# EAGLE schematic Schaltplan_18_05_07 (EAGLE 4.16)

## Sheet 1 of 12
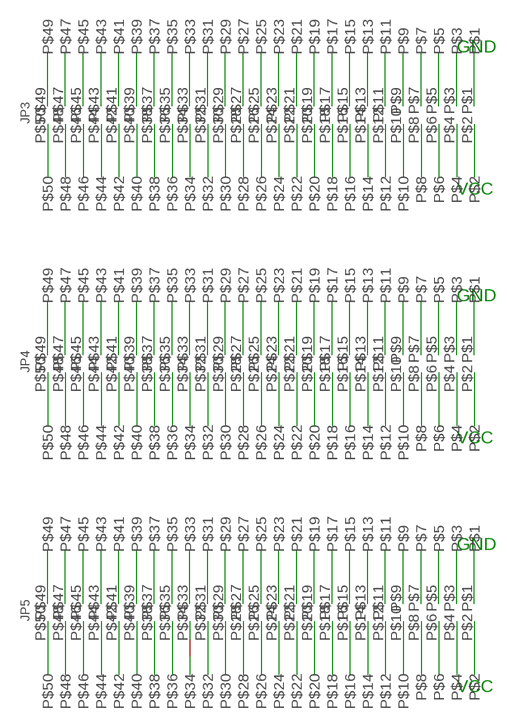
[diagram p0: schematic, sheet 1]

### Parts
JP3  CONN_50POL  [CONN_50POL]
JP4  CONN_50POL  [CONN_50POL]
JP5  CONN_50POL  [CONN_50POL]

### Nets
/NMI: JP3.P$45 ; also sheet 2
/RD: JP3.P$37 ; also sheet 2
/RDY: JP5.P$14 ; also sheet 2
/RESI: JP3.P$41 ; also sheet 2
/RESO: JP3.P$43 ; also sheet 2
/WR: JP3.P$42 ; also sheet 2
A0: JP3.P$6 ; also sheet 2
A1: JP3.P$8 ; also sheet 2
A2: JP3.P$10 ; also sheet 2
A3: JP3.P$12 ; also sheet 2
A4: JP3.P$14 ; also sheet 2
A5: JP3.P$16 ; also sheet 2
A6: JP3.P$18 ; also sheet 2
A7: JP3.P$20 ; also sheet 2
A8: JP3.P$22 ; also sheet 2
A9: JP3.P$24 ; also sheet 2
A10: JP3.P$26 ; also sheet 2
A11: JP3.P$28 ; also sheet 2
A12: JP3.P$30 ; also sheet 2
A13: JP3.P$32 ; also sheet 2
A14: JP3.P$34 ; also sheet 2
A15: JP3.P$36 ; also sheet 2
A16: JP3.P$38 ; also sheet 2
A17: JP3.P$40 ; also sheet 2
A18: JP3.P$46 ; also sheet 2
A19: JP3.P$48 ; also sheet 2
A20: JP3.P$50 ; also sheet 2
A21: JP3.P$49 ; also sheet 2,10
A22: JP3.P$47 ; also sheet 2,10
A23: JP5.P$13 ; also sheet 2
ALE: JP3.P$39 ; also sheet 2
D0: JP3.P$5 ; also sheet 2
D1: JP3.P$7 ; also sheet 2
D2: JP3.P$9 ; also sheet 2
D3: JP3.P$11 ; also sheet 2
D4: JP3.P$13 ; also sheet 2,7
D5: JP3.P$15 ; also sheet 2
D6: JP3.P$17 ; also sheet 2
D7: JP3.P$19 ; also sheet 2
D8: JP3.P$21 ; also sheet 2
D9: JP3.P$23 ; also sheet 2
D10: JP3.P$25 ; also sheet 2
D11: JP3.P$27 ; also sheet 2
D12: JP3.P$29 ; also sheet 2
D13: JP3.P$31 ; also sheet 2
D14: JP3.P$33 ; also sheet 2
D15: JP3.P$35 ; also sheet 2
GND: JP3.P$1 JP3.P$3 JP4.P$1 JP4.P$3 JP5.P$1 JP5.P$3 ; also sheet 2,3,5,6,7,8,9,10,11,12
N$92: JP4.P$18
N$93: JP4.P$16
N$142: JP5.P$18
N$143: JP5.P$16
P2.0: JP4.P$19 ; also sheet 2,8
P2.1: JP4.P$21 ; also sheet 2,8
P2.2: JP4.P$23 ; also sheet 2,8
P2.3: JP4.P$25 ; also sheet 2,8
P2.4: JP4.P$27 ; also sheet 2,8
P2.5: JP4.P$29 ; also sheet 2,8
P2.6: JP4.P$31 ; also sheet 2,8
P2.7: JP4.P$33 ; also sheet 2,8
P2.8: JP4.P$35 ; also sheet 2,9
P2.9: JP4.P$37 ; also sheet 2
P2.10: JP4.P$39 ; also sheet 2
P2.11: JP4.P$41 ; also sheet 2
P2.12: JP4.P$43 ; also sheet 2
P2.13: JP4.P$45 ; also sheet 2
P2.14: JP4.P$47 ; also sheet 2
P2.15: JP4.P$49 ; also sheet 2
P3.0: JP4.P$20 ; also sheet 2
P3.1: JP4.P$22 ; also sheet 2
P3.2: JP4.P$24 ; also sheet 2
P3.3: JP4.P$26 ; also sheet 2,9
P3.4: JP4.P$28 ; also sheet 2,11
P3.5: JP4.P$30 ; also sheet 2,11
P3.6: JP4.P$32 ; also sheet 2,11
P3.7: JP4.P$34 ; also sheet 2,11
P3.8: JP4.P$36 ; also sheet 2,11
P3.9: JP4.P$38 ; also sheet 2,11
P3.10: JP4.P$40 ; also sheet 2,11
P3.11: JP4.P$42 ; also sheet 2,11
P3.12: JP3.P$44 JP4.P$44 ; also sheet 2
P3.13: JP4.P$46 ; also sheet 2
P3.14: JP4.P$48
P3.15: JP4.P$50 ; also sheet 2
P5.0: JP4.P$5 JP5.P$19 ; also sheet 2,6
P5.1: JP4.P$6 JP5.P$21 ; also sheet 2,6
P5.2: JP4.P$7 JP5.P$23 ; also sheet 2,6
P5.3: JP4.P$8 JP5.P$25 ; also sheet 2,6
P5.4: JP4.P$9 JP5.P$27 ; also sheet 2,6
P5.5: JP4.P$10 JP5.P$29 ; also sheet 2,6
P5.6: JP4.P$11 JP5.P$31 ; also sheet 2,6
P5.7: JP4.P$12 JP5.P$33 ; also sheet 2,6
P5.8: JP4.P$13 JP5.P$35 ; also sheet 2,9
P5.9: JP4.P$14 JP5.P$37 ; also sheet 2,9
P5.10: JP5.P$39 ; also sheet 2,4
P5.11: JP5.P$41 ; also sheet 2
P5.12: JP5.P$43 ; also sheet 2,4
P5.13: JP5.P$45 ; also sheet 2
P5.14: JP5.P$47 ; also sheet 2
P5.15: JP5.P$49 ; also sheet 2
P6.0: JP5.P$5 ; also sheet 2
P6.1: JP5.P$6 ; also sheet 2
P6.2: JP5.P$7 ; also sheet 2
P6.3: JP5.P$8 ; also sheet 2
P6.4: JP5.P$9 ; also sheet 2
P6.5: JP5.P$10 ; also sheet 2
P6.6: JP5.P$11 ; also sheet 2
P6.7: JP5.P$12 ; also sheet 2
P7.0: JP5.P$20 ; also sheet 2
P7.1: JP5.P$22 ; also sheet 2
P7.2: JP5.P$24 ; also sheet 2
P7.3: JP5.P$26 ; also sheet 2
P7.4: JP5.P$28 ; also sheet 2,9
P7.5: JP5.P$30 ; also sheet 2,9
P7.6: JP5.P$32 ; also sheet 2,9
P7.7: JP5.P$34 ; also sheet 2,9
P8.0: JP5.P$36 ; also sheet 2
P8.1: JP5.P$38 ; also sheet 2
P8.2: JP5.P$40 ; also sheet 2
P8.3: JP5.P$42 ; also sheet 2
P8.4: JP5.P$44 ; also sheet 2
P8.5: JP5.P$46 ; also sheet 2
P8.6: JP5.P$48 ; also sheet 2
P8.7: JP5.P$50 ; also sheet 2
VAGND: JP4.P$15 JP5.P$15 ; also sheet 2,3,4
VAREF: JP4.P$17 JP5.P$17 ; also sheet 2,3
VCC2: JP3.P$2 JP3.P$4 JP4.P$2 JP4.P$4 JP5.P$2 JP5.P$4 ; also sheet 3,4,6,8,9,10,11

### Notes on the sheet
- GND
- VCC
- GND
- VCC
- GND
- VCC

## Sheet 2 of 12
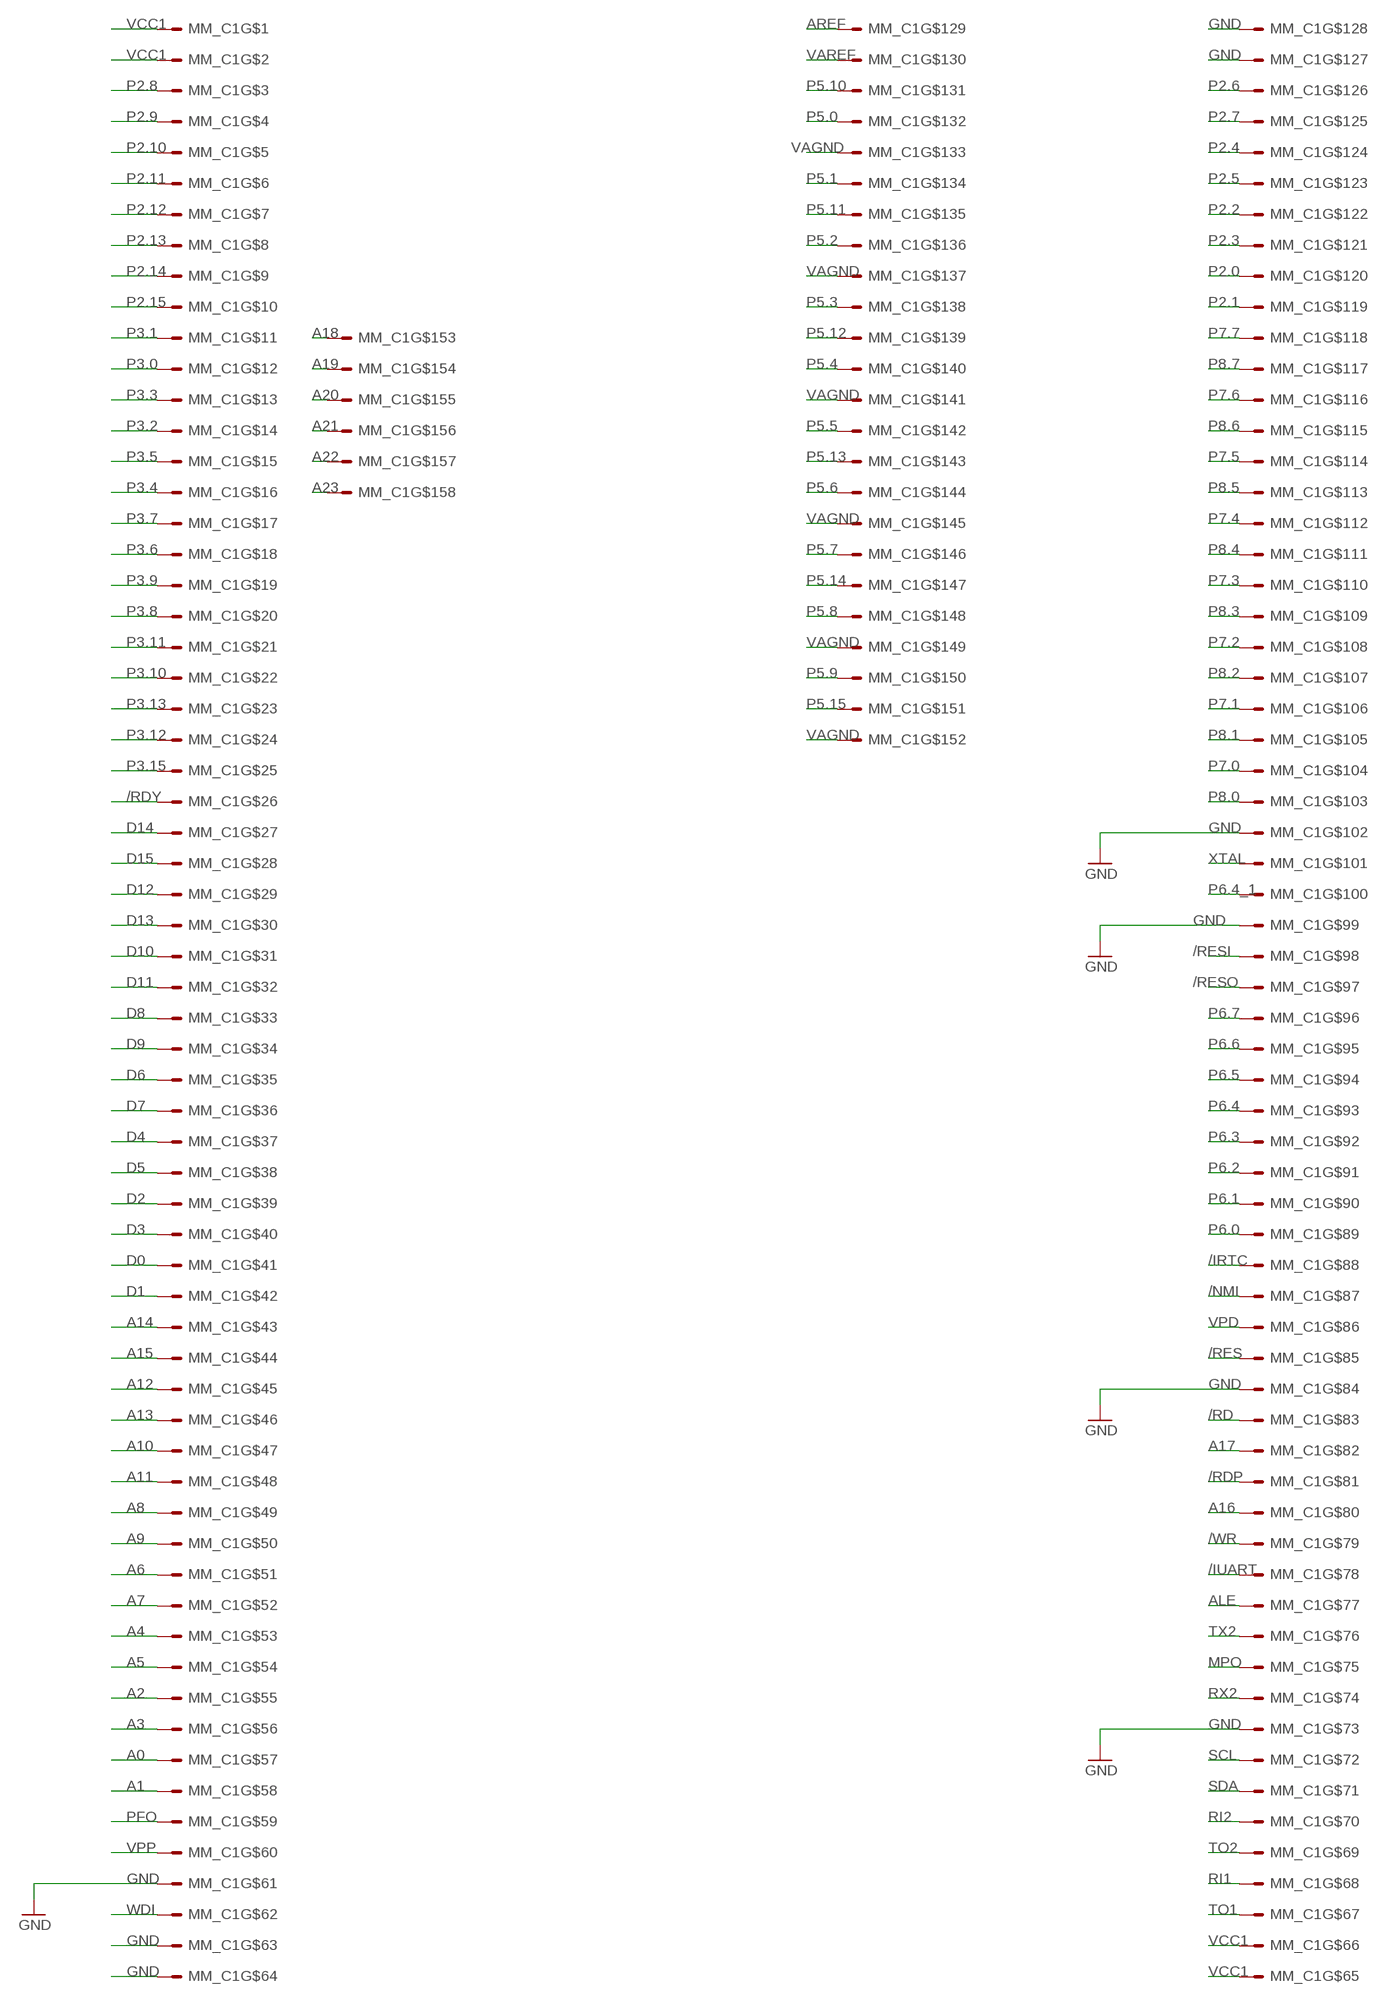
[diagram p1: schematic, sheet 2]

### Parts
MM_C1  MM_C167  [MM_GES]

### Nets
/IRTC: MM_C1.88 ; also sheet 12
/IUART: MM_C1.78
/NMI: MM_C1.87 ; also sheet 1
/RD: MM_C1.83 ; also sheet 1
/RDP: MM_C1.81
/RDY: MM_C1.26 ; also sheet 1
/RES: MM_C1.85 ; also sheet 7
/RESI: MM_C1.98 ; also sheet 1
/RESO: MM_C1.97 ; also sheet 1
/WR: MM_C1.79 ; also sheet 1
A0: MM_C1.57 ; also sheet 1
A1: MM_C1.58 ; also sheet 1
A2: MM_C1.55 ; also sheet 1
A3: MM_C1.56 ; also sheet 1
A4: MM_C1.53 ; also sheet 1
A5: MM_C1.54 ; also sheet 1
A6: MM_C1.51 ; also sheet 1
A7: MM_C1.52 ; also sheet 1
A8: MM_C1.49 ; also sheet 1
A9: MM_C1.50 ; also sheet 1
A10: MM_C1.47 ; also sheet 1
A11: MM_C1.48 ; also sheet 1
A12: MM_C1.45 ; also sheet 1
A13: MM_C1.46 ; also sheet 1
A14: MM_C1.43 ; also sheet 1
A15: MM_C1.44 ; also sheet 1
A16: MM_C1.80 ; also sheet 1
A17: MM_C1.82 ; also sheet 1
A18: MM_C1.153 ; also sheet 1
A19: MM_C1.154 ; also sheet 1
A20: MM_C1.155 ; also sheet 1
A21: MM_C1.156 ; also sheet 1,10
A22: MM_C1.157 ; also sheet 1,10
A23: MM_C1.158 ; also sheet 1
ALE: MM_C1.77 ; also sheet 1
AREF: MM_C1.129
D0: MM_C1.41 ; also sheet 1
D1: MM_C1.42 ; also sheet 1
D2: MM_C1.39 ; also sheet 1
D3: MM_C1.40 ; also sheet 1
D4: MM_C1.37 ; also sheet 1,7
D5: MM_C1.38 ; also sheet 1
D6: MM_C1.35 ; also sheet 1
D7: MM_C1.36 ; also sheet 1
D8: MM_C1.33 ; also sheet 1
D9: MM_C1.34 ; also sheet 1
D10: MM_C1.31 ; also sheet 1
D11: MM_C1.32 ; also sheet 1
D12: MM_C1.29 ; also sheet 1
D13: MM_C1.30 ; also sheet 1
D14: MM_C1.27 ; also sheet 1
D15: MM_C1.28 ; also sheet 1
GND: MM_C1.61 MM_C1.63 MM_C1.64 MM_C1.73 MM_C1.84 MM_C1.99 MM_C1.102 MM_C1.127 MM_C1.128 ; also sheet 1,3,5,6,7,8,9,10,11,12
MPO: MM_C1.75
P2.0: MM_C1.120 ; also sheet 1,8
P2.1: MM_C1.119 ; also sheet 1,8
P2.2: MM_C1.122 ; also sheet 1,8
P2.3: MM_C1.121 ; also sheet 1,8
P2.4: MM_C1.124 ; also sheet 1,8
P2.5: MM_C1.123 ; also sheet 1,8
P2.6: MM_C1.126 ; also sheet 1,8
P2.7: MM_C1.125 ; also sheet 1,8
P2.8: MM_C1.3 ; also sheet 1,9
P2.9: MM_C1.4 ; also sheet 1
P2.10: MM_C1.5 ; also sheet 1
P2.11: MM_C1.6 ; also sheet 1
P2.12: MM_C1.7 ; also sheet 1
P2.13: MM_C1.8 ; also sheet 1
P2.14: MM_C1.9 ; also sheet 1
P2.15: MM_C1.10 ; also sheet 1
P3.0: MM_C1.12 ; also sheet 1
P3.1: MM_C1.11 ; also sheet 1
P3.2: MM_C1.14 ; also sheet 1
P3.3: MM_C1.13 ; also sheet 1,9
P3.4: MM_C1.16 ; also sheet 1,11
P3.5: MM_C1.15 ; also sheet 1,11
P3.6: MM_C1.18 ; also sheet 1,11
P3.7: MM_C1.17 ; also sheet 1,11
P3.8: MM_C1.20 ; also sheet 1,11
P3.9: MM_C1.19 ; also sheet 1,11
P3.10: MM_C1.22 ; also sheet 1,11
P3.11: MM_C1.21 ; also sheet 1,11
P3.12: MM_C1.24 ; also sheet 1
P3.13: MM_C1.23 ; also sheet 1
P3.15: MM_C1.25 ; also sheet 1
P5.0: MM_C1.132 ; also sheet 1,6
P5.1: MM_C1.134 ; also sheet 1,6
P5.2: MM_C1.136 ; also sheet 1,6
P5.3: MM_C1.138 ; also sheet 1,6
P5.4: MM_C1.140 ; also sheet 1,6
P5.5: MM_C1.142 ; also sheet 1,6
P5.6: MM_C1.144 ; also sheet 1,6
P5.7: MM_C1.146 ; also sheet 1,6
P5.8: MM_C1.148 ; also sheet 1,9
P5.9: MM_C1.150 ; also sheet 1,9
P5.10: MM_C1.131 ; also sheet 1,4
P5.11: MM_C1.135 ; also sheet 1
P5.12: MM_C1.139 ; also sheet 1,4
P5.13: MM_C1.143 ; also sheet 1
P5.14: MM_C1.147 ; also sheet 1
P5.15: MM_C1.151 ; also sheet 1
P6.0: MM_C1.89 ; also sheet 1
P6.1: MM_C1.90 ; also sheet 1
P6.2: MM_C1.91 ; also sheet 1
P6.3: MM_C1.92 ; also sheet 1
P6.4: MM_C1.93 ; also sheet 1
P6.4_1: MM_C1.100
P6.5: MM_C1.94 ; also sheet 1
P6.6: MM_C1.95 ; also sheet 1
P6.7: MM_C1.96 ; also sheet 1
P7.0: MM_C1.104 ; also sheet 1
P7.1: MM_C1.106 ; also sheet 1
P7.2: MM_C1.108 ; also sheet 1
P7.3: MM_C1.110 ; also sheet 1
P7.4: MM_C1.112 ; also sheet 1,9
P7.5: MM_C1.114 ; also sheet 1,9
P7.6: MM_C1.116 ; also sheet 1,9
P7.7: MM_C1.118 ; also sheet 1,9
P8.0: MM_C1.103 ; also sheet 1
P8.1: MM_C1.105 ; also sheet 1
P8.2: MM_C1.107 ; also sheet 1
P8.3: MM_C1.109 ; also sheet 1
P8.4: MM_C1.111 ; also sheet 1
P8.5: MM_C1.113 ; also sheet 1
P8.6: MM_C1.115 ; also sheet 1
P8.7: MM_C1.117 ; also sheet 1
PFO: MM_C1.59
RI1: MM_C1.68 ; also sheet 5
RI2: MM_C1.70 ; also sheet 5
RX2: MM_C1.74
SCL: MM_C1.72 ; also sheet 12
SDA: MM_C1.71 ; also sheet 12
TO1: MM_C1.67 ; also sheet 5
TO2: MM_C1.69 ; also sheet 5
TX2: MM_C1.76
VAGND: MM_C1.133 MM_C1.137 MM_C1.141 MM_C1.145 MM_C1.149 MM_C1.152 ; also sheet 1,3,4
VAREF: MM_C1.130 ; also sheet 1,3
VCC1: MM_C1.1 MM_C1.2 MM_C1.65 MM_C1.66 ; also sheet 3
VPD: MM_C1.86
VPP: MM_C1.60
WDI: MM_C1.62
XTAL: MM_C1.101

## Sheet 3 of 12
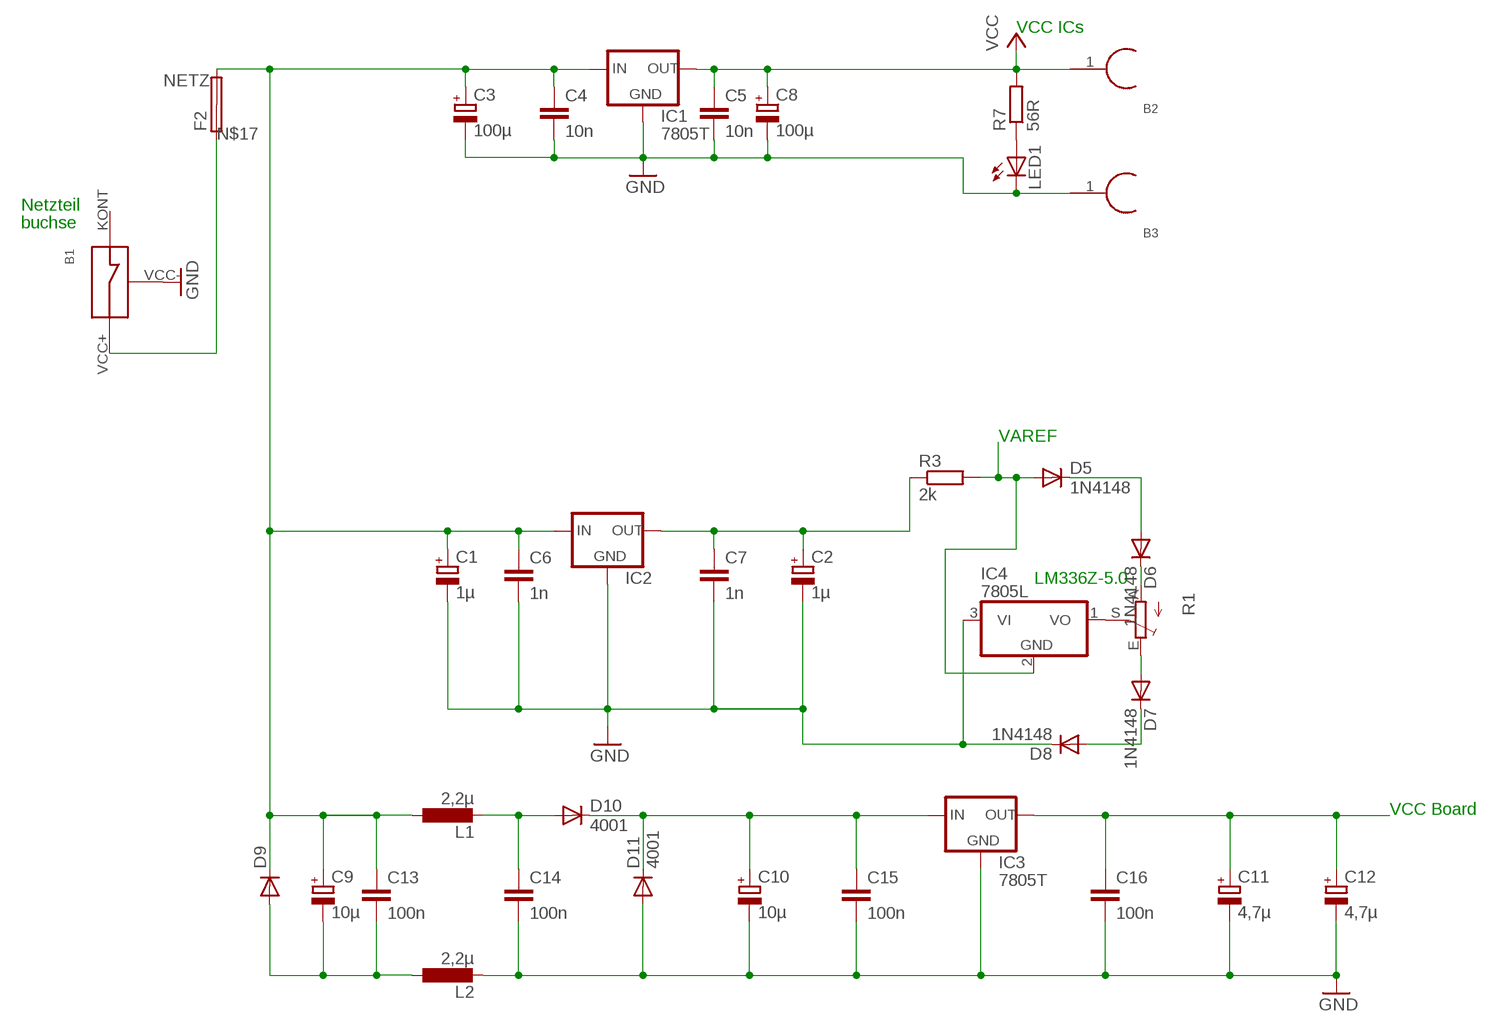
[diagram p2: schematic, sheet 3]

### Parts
B1  NETZBUCHSE  [NETZBUCHSE]
B2  BUCHSE01  [BUCHSE01]
B3  BUCHSE01  [BUCHSE01]
C1  1µ  CPOL-EUCT6032  [CT6032]
C2  1µ  CPOL-EUCT6032  [CT6032]
C3  100µ  CPOL-EUCT6032  [CT6032]
C4  10n  C-EUC0603  [C0603]
C5  10n  C-EUC0603  [C0603]
C6  1n  C-EUC0603  [C0603]
C7  1n  C-EUC0603  [C0603]
C8  100µ  CPOL-EUCT6032  [CT6032]
C9  10µ  CPOL-EUCT6032  [CT6032]
C10  10µ  CPOL-EUCT6032  [CT6032]
C11  4,7µ  CPOL-EUR/2012-12W  [R/2012-12W]
C12  4,7µ  CPOL-EUR/2012-12W  [R/2012-12W]
C13  100n  C-EUC0603  [C0603]
C14  100n  C-EUC0603  [C0603]
C15  100n  C-EUC0603  [C0603]
C16  100n  C-EUC0603  [C0603]
D5  1N4148  DIODE-MELF-MLL41  [MELF-MLL41]
D6  1N4148  DIODE-MELF-MLL41  [MELF-MLL41]
D7  1N4148  DIODE-MELF-MLL41  [MELF-MLL41]
D8  1N4148  DIODE-MELF-MLL41  [MELF-MLL41]
D9  DIODE-SOD110-W  [SOD110-W]
D10  4001  DIODE-MELF-MLL41  [MELF-MLL41]
D11  4001  DIODE-MELF-MLL41  [MELF-MLL41]
F2  SHK20Q  [SHK20Q]
IC1  7805T  78XXS  [78XXS]
IC2  78LXX  [78LXX]
IC3  7805T  78XXS  [78XXS]
IC4  7805L  [TO92]
L1  2,2µ  L-EUL1812  [L1812]
L2  2,2µ  L-EUL1812  [L1812]
LED1  LED5MM  [LED5MM]
R1  TRIM_EU-LI10  [LI10]
R3  2k  R-EU_R0603  [R0603]
R7  56R  R-EU_R0603  [R0603]

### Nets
GND: B1.VCC- B3.1 C3.- C4.2 C5.2 C8.- C10.- C11.- C12.- C14.2 C15.2 C16.2 D11.A IC1.GND IC3.GND L2.2 LED1.K(C) ; also sheet 1,2,5,6,7,8,9,10,11,12
N$3: IC4.1(VO) R1.S
N$6: D6.C R1.A
N$7: D7.A R1.E
N$8: C2.+ C7.1 IC2.OUT R3.1
N$9: D5.C D6.A
N$11: C14.1 D10.A L1.2
N$12: C10.+ C15.1 D10.C D11.C IC3.IN
N$13: D7.C D8.A
N$15: LED1.A R7.1
N$17: B1.VCC+ F2.1A
N$151: C9.- C13.2 D9.A L2.1
NETZ: C1.+ C3.+ C4.1 C6.1 C9.+ C13.1 D9.C F2.2A IC1.IN IC2.IN L1.1
VAGND: C1.- C2.- C6.2 C7.2 D8.C IC2.GND IC4.3(VI) ; supply symbol labelled GND ; also sheet 1,2,4
VAREF: D5.A IC4.2(GND) R3.2 ; also sheet 1,2
VCC1: C11.+ C12.+ C16.1 IC3.OUT ; also sheet 2
VCC2: B2.1 C5.1 C8.+ IC1.OUT R7.2 ; supply symbol labelled VCC ; also sheet 1,4,6,8,9,10,11
Unconnected: B1.KONT F2.1B F2.2B

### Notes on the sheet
- VCC ICs
- Netzteil
- buchse
- VAREF
- LM336Z-5.0
- VCC Board

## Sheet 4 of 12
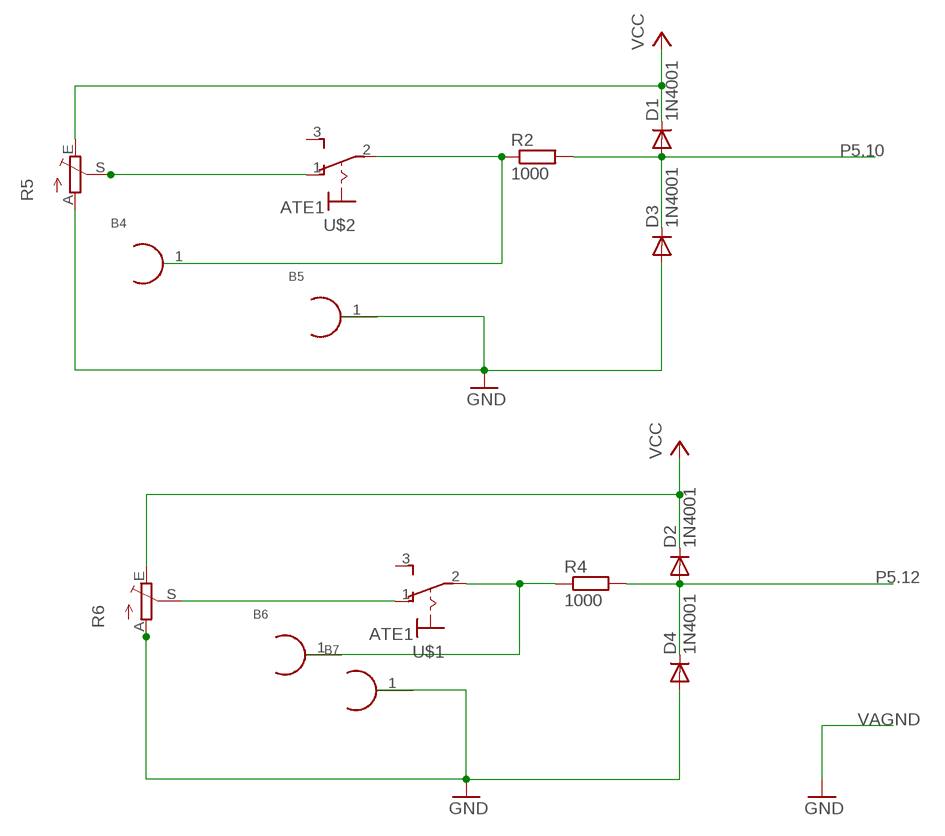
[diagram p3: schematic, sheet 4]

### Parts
B4  BUCHSE01  [BUCHSE01]
B5  BUCHSE01  [BUCHSE01]
B6  BUCHSE01  [BUCHSE01]
B7  BUCHSE01  [BUCHSE01]
D1  1N4001  DIODE-MELF-MLL41  [MELF-MLL41]
D2  1N4001  DIODE-MELF-MLL41  [MELF-MLL41]
D3  1N4001  DIODE-MELF-MLL41  [MELF-MLL41]
D4  1N4001  DIODE-MELF-MLL41  [MELF-MLL41]
R2  1000  R-EU_R0603  [R0603]
R4  1000  R-EU_R0603  [R0603]
R5  TRIM_EU-LI15  [LI15]
R6  TRIM_EU-LI15  [LI15]
U$1  ATE1  [ATE1]
U$2  ATE1  [ATE1]

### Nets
B4: B4.1 R2.1 U$2.2
BUCHSE: B6.1 R4.1 U$1.2
N$4: R6.S U$1.1
N$10: R5.S U$2.1
P5.10: D1.A D3.C R2.2 ; also sheet 1,2
P5.12: D2.A D4.C R4.2 ; also sheet 1,2
VAGND: B5.1 B7.1 D3.A D4.A R5.A R6.A ; supply symbol labelled GND ; also sheet 1,2,3
VCC2: D1.C D2.C R5.E R6.E ; supply symbol labelled VCC ; also sheet 1,3,6,8,9,10,11
Unconnected: U$1.3 U$2.3

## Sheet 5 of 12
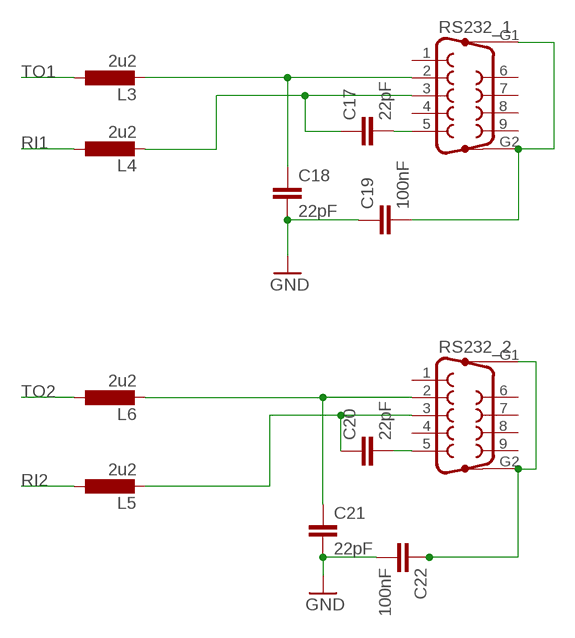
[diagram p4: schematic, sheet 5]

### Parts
C17  22pF  C-EUC0603  [C0603]
C18  22pF  C-EUC0603  [C0603]
C19  100nF  C-EUC0603  [C0603]
C20  22pF  C-EUC0603  [C0603]
C21  22pF  C-EUC0603  [C0603]
C22  100nF  C-EUC0603  [C0603]
L3  2u2  L-EUL1812  [L1812]
L4  2u2  L-EUL1812  [L1812]
L5  2u2  L-EUL1812  [L1812]
L6  2u2  L-EUL1812  [L1812]
RS232_1  F09HP  [F09HP]
RS232_2  F09HP  [F09HP]

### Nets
GND: C18.2 C19.1 C21.2 C22.2 ; also sheet 1,2,3,6,7,8,9,10,11,12
N$14: C22.1 RS232_2.G1 RS232_2.G2
N$16: C20.2 RS232_2.5
N$18: C19.2 RS232_1.G1 RS232_1.G2
N$19: C18.1 L3.2 RS232_1.2
N$20: C17.2 RS232_1.5
N$21: C17.1 L4.2 RS232_1.3
RI1: L4.1 ; also sheet 2
RI2: L5.1 ; also sheet 2
RXD: C20.1 L5.2 RS232_2.3
TO1: L3.1 ; also sheet 2
TO2: L6.1 ; also sheet 2
TXD: C21.1 L6.2 RS232_2.2
Unconnected: RS232_1.1 RS232_1.4 RS232_1.6 RS232_1.7 RS232_1.8 RS232_1.9 RS232_2.1 RS232_2.4 RS232_2.6 RS232_2.7 RS232_2.8 RS232_2.9

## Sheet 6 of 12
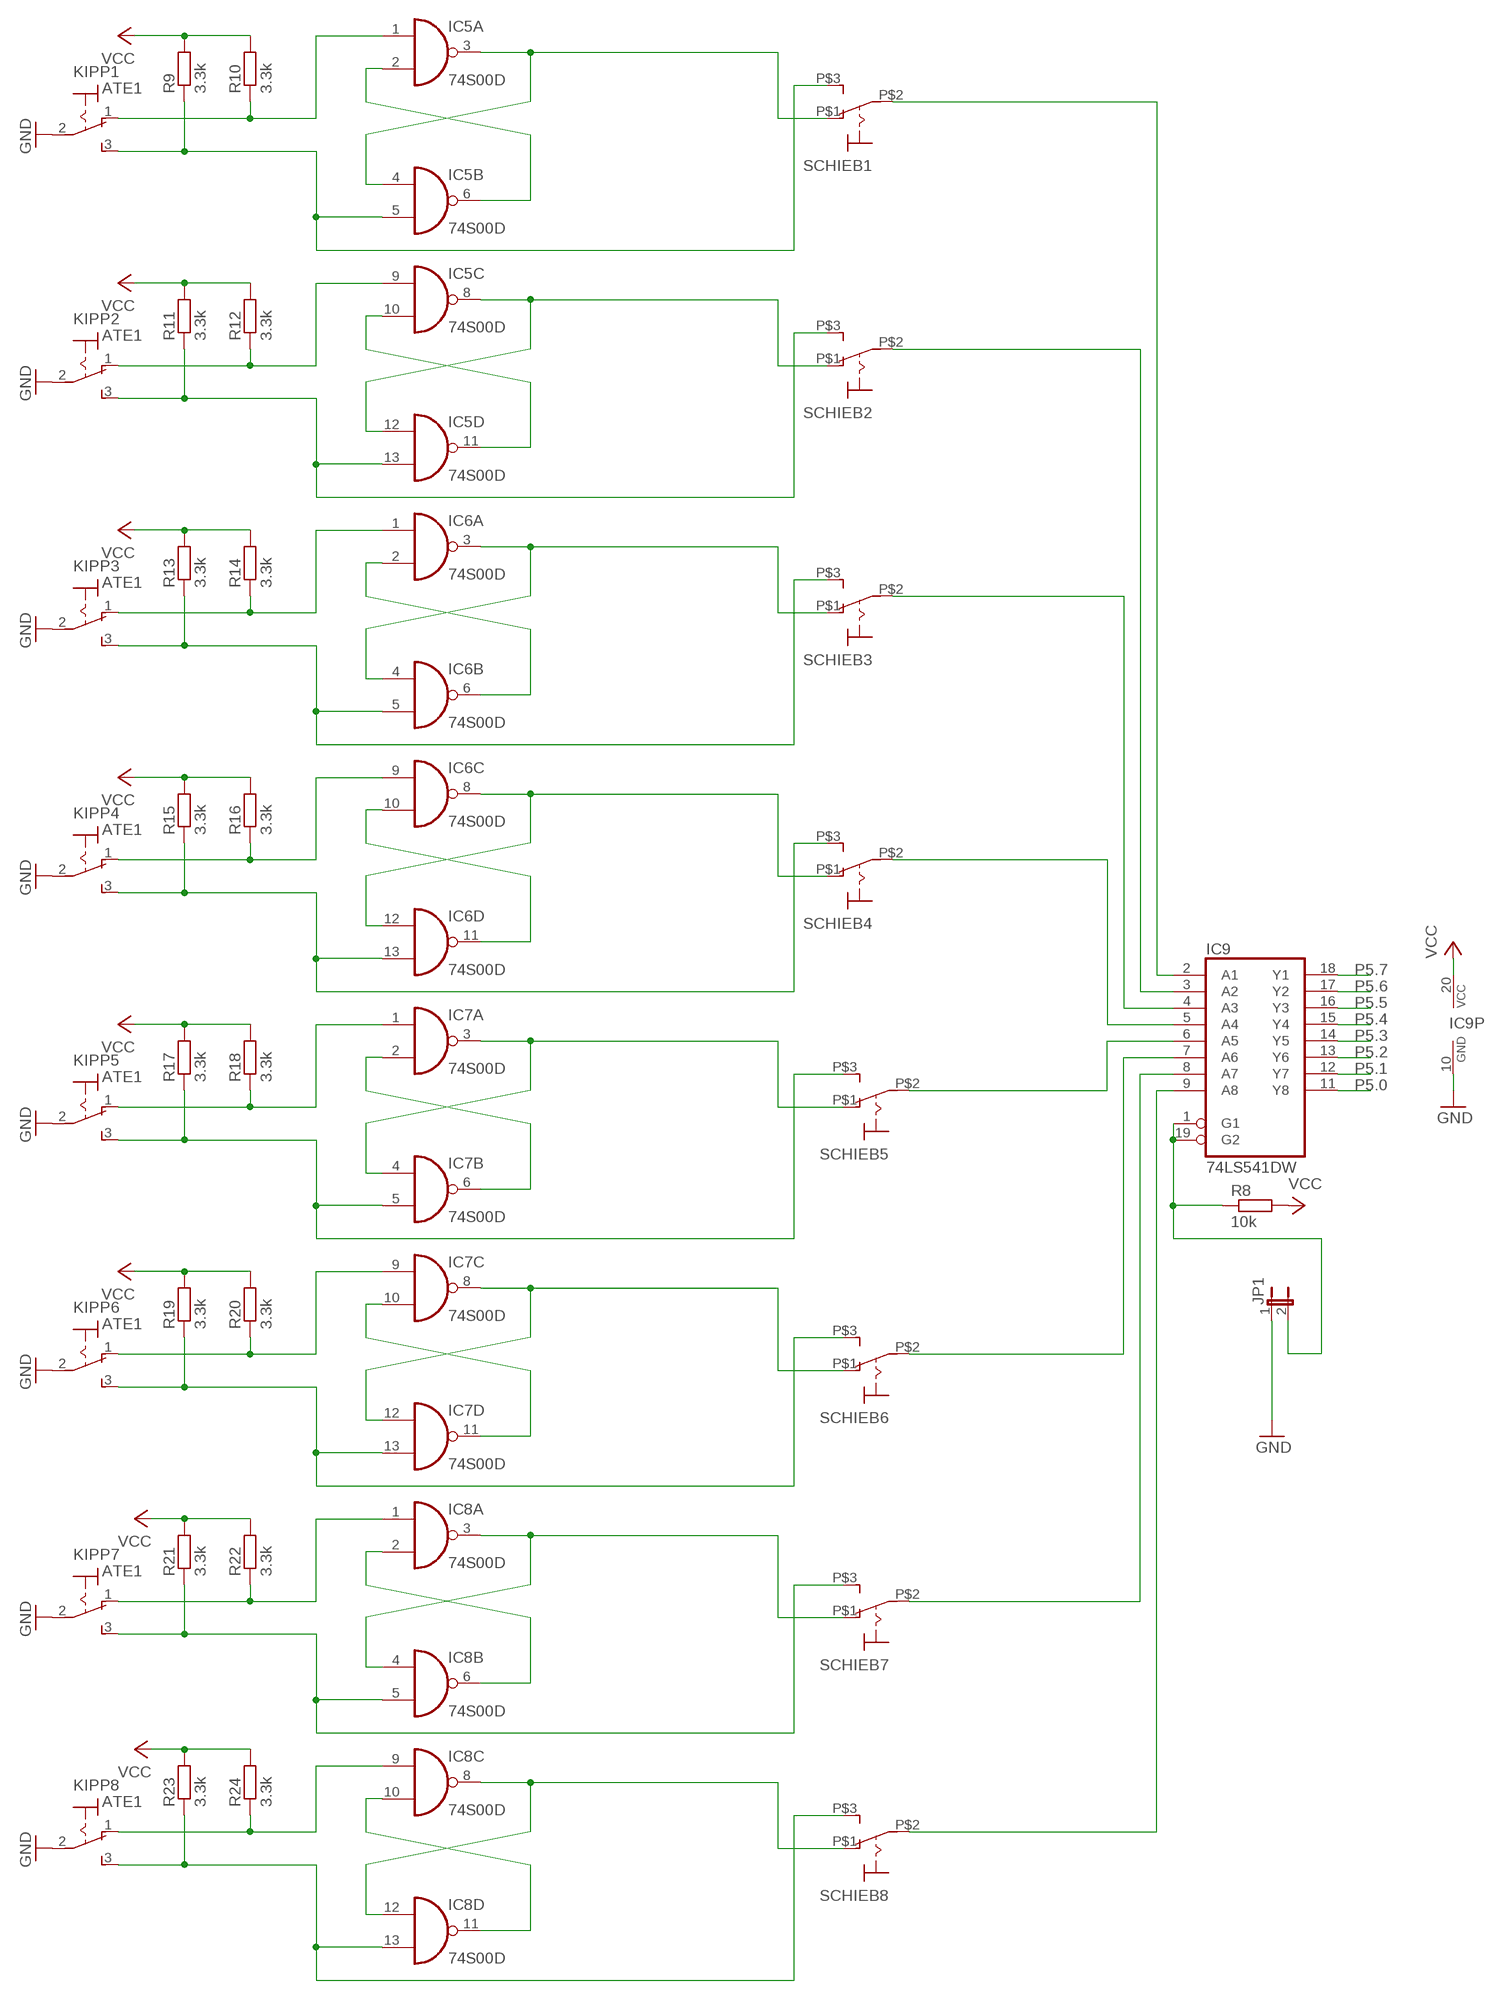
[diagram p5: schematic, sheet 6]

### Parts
IC5  74S00D  [SO14]
IC6  74S00D  [SO14]
IC7  74S00D  [SO14]
IC8  74S00D  [SO14]
IC9  74LS541DW  [SO20W]
JP1  JP1E  [JP1]
KIPP1  ATE1  [ATE1]
KIPP2  ATE1  [ATE1]
KIPP3  ATE1  [ATE1]
KIPP4  ATE1  [ATE1]
KIPP5  ATE1  [ATE1]
KIPP6  ATE1  [ATE1]
KIPP7  ATE1  [ATE1]
KIPP8  ATE1  [ATE1]
R8  10k  R-0603  [R0603]
R9  3.3k  R-0603  [R0603]
R10  3.3k  R-0603  [R0603]
R11  3.3k  R-0603  [R0603]
R12  3.3k  R-0603  [R0603]
R13  3.3k  R-0603  [R0603]
R14  3.3k  R-0603  [R0603]
R15  3.3k  R-0603  [R0603]
R16  3.3k  R-0603  [R0603]
R17  3.3k  R-0603  [R0603]
R18  3.3k  R-0603  [R0603]
R19  3.3k  R-0603  [R0603]
R20  3.3k  R-0603  [R0603]
R21  3.3k  R-0603  [R0603]
R22  3.3k  R-0603  [R0603]
R23  3.3k  R-0603  [R0603]
R24  3.3k  R-0603  [R0603]
SCHIEB1  SCHIEBESCHALTER_WECHSLER  [SCHIEBESCHALTER]
SCHIEB2  SCHIEBESCHALTER_WECHSLER  [SCHIEBESCHALTER]
SCHIEB3  SCHIEBESCHALTER_WECHSLER  [SCHIEBESCHALTER]
SCHIEB4  SCHIEBESCHALTER_WECHSLER  [SCHIEBESCHALTER]
SCHIEB5  SCHIEBESCHALTER_WECHSLER  [SCHIEBESCHALTER]
SCHIEB6  SCHIEBESCHALTER_WECHSLER  [SCHIEBESCHALTER]
SCHIEB7  SCHIEBESCHALTER_WECHSLER  [SCHIEBESCHALTER]
SCHIEB8  SCHIEBESCHALTER_WECHSLER  [SCHIEBESCHALTER]

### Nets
GND: IC9.10(GND) JP1.1 KIPP1.2 KIPP2.2 KIPP3.2 KIPP4.2 KIPP5.2 KIPP6.2 KIPP7.2 KIPP8.2 ; also sheet 1,2,3,5,7,8,9,10,11,12
N$22: IC5.1(A:I0) KIPP1.1 R10.1
N$23: IC5.3(A:O) IC5.4(B:I0) SCHIEB1.P$1
N$24: IC5.5(B:I1) KIPP1.3 R9.1 SCHIEB1.P$3
N$25: IC5.2(A:I1) IC5.6(B:O)
N$26: IC5.9(C:I0) KIPP2.1 R12.1
N$27: IC5.13(D:I1) KIPP2.3 R11.1 SCHIEB2.P$3
N$28: IC5.8(C:O) IC5.12(D:I0) SCHIEB2.P$1
N$29: IC5.10(C:I1) IC5.11(D:O)
N$30: IC6.1(A:I0) KIPP3.1 R14.1
N$31: IC6.5(B:I1) KIPP3.3 R13.1 SCHIEB3.P$3
N$32: IC6.3(A:O) IC6.4(B:I0) SCHIEB3.P$1
N$33: IC6.2(A:I1) IC6.6(B:O)
N$35: IC6.9(C:I0) KIPP4.1 R16.1
N$36: IC6.13(D:I1) KIPP4.3 R15.1 SCHIEB4.P$3
N$37: IC6.8(C:O) IC6.12(D:I0) SCHIEB4.P$1
N$38: IC6.10(C:I1) IC6.11(D:O)
N$39: IC7.1(A:I0) KIPP5.1 R18.1
N$40: IC7.5(B:I1) KIPP5.3 R17.1 SCHIEB5.P$3
N$41: IC7.3(A:O) IC7.4(B:I0) SCHIEB5.P$1
N$42: IC7.2(A:I1) IC7.6(B:O)
N$43: IC7.9(C:I0) KIPP6.1 R20.1
N$44: IC7.13(D:I1) KIPP6.3 R19.1 SCHIEB6.P$3
N$45: IC7.8(C:O) IC7.12(D:I0) SCHIEB6.P$1
N$46: IC7.10(C:I1) IC7.11(D:O)
N$47: IC8.1(A:I0) KIPP7.1 R22.1
N$48: IC8.5(B:I1) KIPP7.3 R21.1 SCHIEB7.P$3
N$49: IC8.3(A:O) IC8.4(B:I0) SCHIEB7.P$1
N$50: IC8.2(A:I1) IC8.6(B:O)
N$53: IC8.9(C:I0) KIPP8.1 R24.1
N$54: IC8.13(D:I1) KIPP8.3 R23.1 SCHIEB8.P$3
N$55: IC8.8(C:O) IC8.12(D:I0) SCHIEB8.P$1
N$56: IC8.10(C:I1) IC8.11(D:O)
N$57: IC9.2(A1) SCHIEB1.P$2
N$58: IC9.3(A2) SCHIEB2.P$2
N$59: IC9.4(A3) SCHIEB3.P$2
N$60: IC9.5(A4) SCHIEB4.P$2
N$61: IC9.9(A8) SCHIEB8.P$2
N$62: IC9.8(A7) SCHIEB7.P$2
N$63: IC9.7(A6) SCHIEB6.P$2
N$64: IC9.6(A5) SCHIEB5.P$2
N$65: IC9.1(G1) IC9.19(G2) JP1.2 R8.1
P5.0: IC9.11(Y8) ; also sheet 1,2
P5.1: IC9.12(Y7) ; also sheet 1,2
P5.2: IC9.13(Y6) ; also sheet 1,2
P5.3: IC9.14(Y5) ; also sheet 1,2
P5.4: IC9.15(Y4) ; also sheet 1,2
P5.5: IC9.16(Y3) ; also sheet 1,2
P5.6: IC9.17(Y2) ; also sheet 1,2
P5.7: IC9.18(Y1) ; also sheet 1,2
VCC2: IC9.20(VCC) R8.2 R9.2 R10.2 R11.2 R12.2 R13.2 R14.2 R15.2 R16.2 R17.2 R18.2 R19.2 R20.2 R21.2 R22.2 R23.2 R24.2 ; supply symbol labelled VCC ; also sheet 1,3,4,8,9,10,11

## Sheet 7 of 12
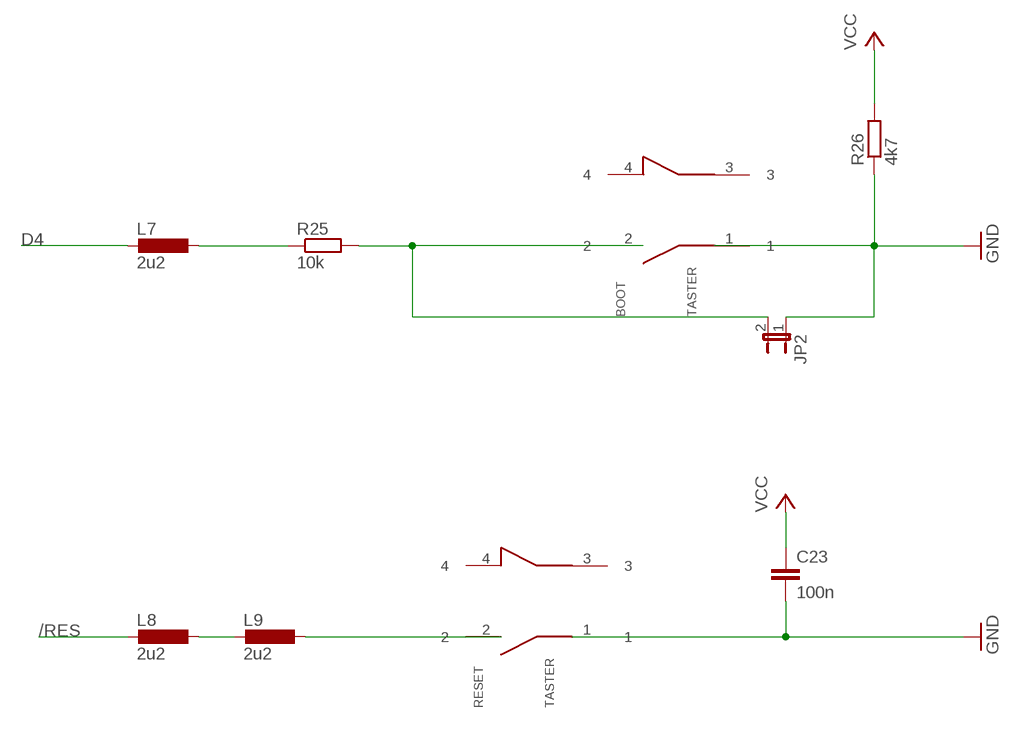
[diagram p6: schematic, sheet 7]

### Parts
BOOT  TASTER  [TASTER]
C23  100n  C-EUC0603  [C0603]
JP2  JP1E  [JP1]
L7  2u2  L-EUL1812  [L1812]
L8  2u2  L-EUL1812  [L1812]
L9  2u2  L-EUL1812  [L1812]
R25  10k  R-EU_R0603  [R0603]
R26  4k7  R-EU_R0603  [R0603]
RESET  TASTER  [TASTER]

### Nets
/RES: L8.2 ; also sheet 2
D4: L7.2 ; also sheet 1,2
GND: BOOT.1 C23.2 JP2.1 R26.1 RESET.1 ; also sheet 1,2,3,5,6,8,9,10,11,12
N$34: L7.1 R25.1
N$66: BOOT.2 JP2.2 R25.2
N$67: L9.1 RESET.2
N$68: L8.1 L9.2
VCC: C23.1 R26.2
Unconnected: BOOT.3 BOOT.4 RESET.3 RESET.4

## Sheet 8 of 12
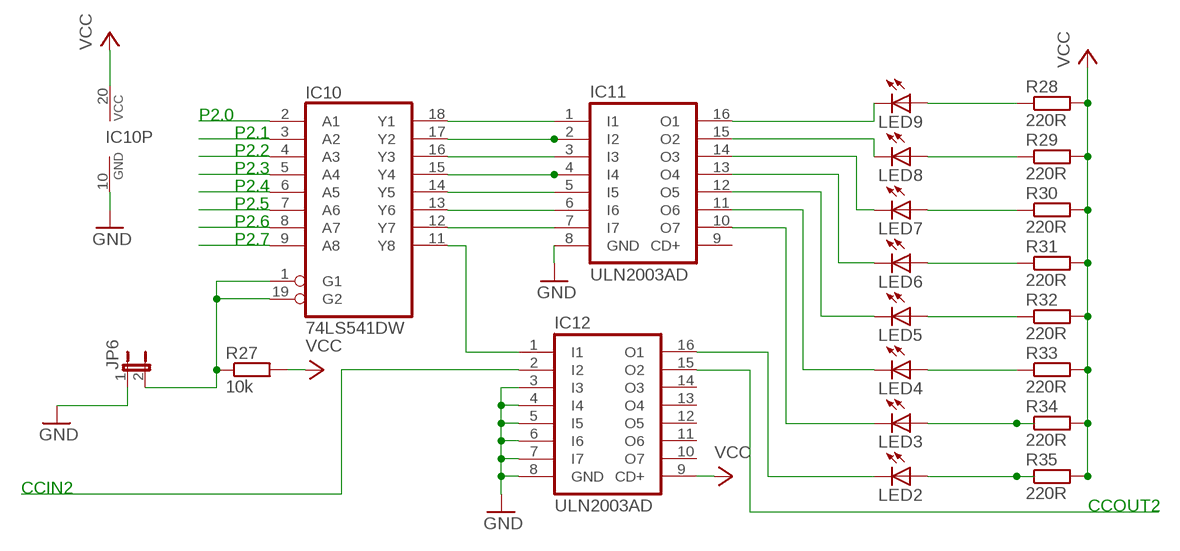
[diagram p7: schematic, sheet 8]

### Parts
IC10  74LS541DW  [SO20W]
IC11  ULN2003AD  [SO16]
IC12  ULN2003AD  [SO16]
JP6  JP1E  [JP1]
LED2  LEDCHIPLED_0603  [CHIPLED_0603]
LED3  LEDCHIPLED_0603  [CHIPLED_0603]
LED4  LEDCHIPLED_0603  [CHIPLED_0603]
LED5  LEDCHIPLED_0603  [CHIPLED_0603]
LED6  LEDCHIPLED_0603  [CHIPLED_0603]
LED7  LEDCHIPLED_0603  [CHIPLED_0603]
LED8  LEDCHIPLED_0603  [CHIPLED_0603]
LED9  LEDCHIPLED_0603  [CHIPLED_0603]
R27  10k  R-0603  [R0603]
R28  220R  R-0603  [R0603]
R29  220R  R-0603  [R0603]
R30  220R  R-0603  [R0603]
R31  220R  R-0603  [R0603]
R32  220R  R-0603  [R0603]
R33  220R  R-0603  [R0603]
R34  220R  R-0603  [R0603]
R35  220R  R-0603  [R0603]

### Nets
CCIN2: IC12.2(I2) ; also sheet 9
CCOUT2: IC12.15(O2) ; also sheet 9
GND: IC10.10(GND) IC11.8(GND) IC12.3(I3) IC12.4(I4) IC12.5(I5) IC12.6(I6) IC12.7(I7) IC12.8(GND) JP6.1 ; also sheet 1,2,3,5,6,7,9,10,11,12
N$70: IC10.1(G1) IC10.19(G2) JP6.2 R27.1
N$71: IC10.18(Y1) IC11.1(I1)
N$72: IC10.17(Y2) IC11.2(I2)
N$73: IC10.16(Y3) IC11.3(I3)
N$74: IC10.15(Y4) IC11.4(I4)
N$75: IC10.14(Y5) IC11.5(I5)
N$76: IC10.13(Y6) IC11.6(I6)
N$77: IC10.12(Y7) IC11.7(I7)
N$78: IC10.11(Y8) IC12.1(I1)
N$80: LED2.A R35.1
N$81: LED3.A R34.1
N$82: LED4.A R33.1
N$83: LED5.A R32.1
N$84: LED6.A R31.1
N$85: LED7.A R30.1
N$86: LED8.A R29.1
N$87: LED9.A R28.1
N$88: IC12.16(O1) LED2.C
N$89: IC11.10(O7) LED3.C
N$90: IC11.11(O6) LED4.C
N$91: IC11.12(O5) LED5.C
N$94: IC11.13(O4) LED6.C
N$95: IC11.14(O3) LED7.C
N$96: IC11.15(O2) LED8.C
N$97: IC11.16(O1) LED9.C
P2.0: IC10.2(A1) ; also sheet 1,2
P2.1: IC10.3(A2) ; also sheet 1,2
P2.2: IC10.4(A3) ; also sheet 1,2
P2.3: IC10.5(A4) ; also sheet 1,2
P2.4: IC10.6(A5) ; also sheet 1,2
P2.5: IC10.7(A6) ; also sheet 1,2
P2.6: IC10.8(A7) ; also sheet 1,2
P2.7: IC10.9(A8) ; also sheet 1,2
VCC2: IC10.20(VCC) IC12.9(CD+) R27.2 R28.2 R29.2 R30.2 R31.2 R32.2 R33.2 R34.2 R35.2 ; supply symbol labelled VCC ; also sheet 1,3,4,6,9,10,11
Unconnected: IC11.9(CD+) IC12.10(O7) IC12.11(O6) IC12.12(O5) IC12.13(O4) IC12.14(O3)

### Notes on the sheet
- P2.0
- P2.1
- P2.2
- P2.3
- P2.4
- P2.5
- P2.6
- P2.7
- CCIN2
- CCOUT2

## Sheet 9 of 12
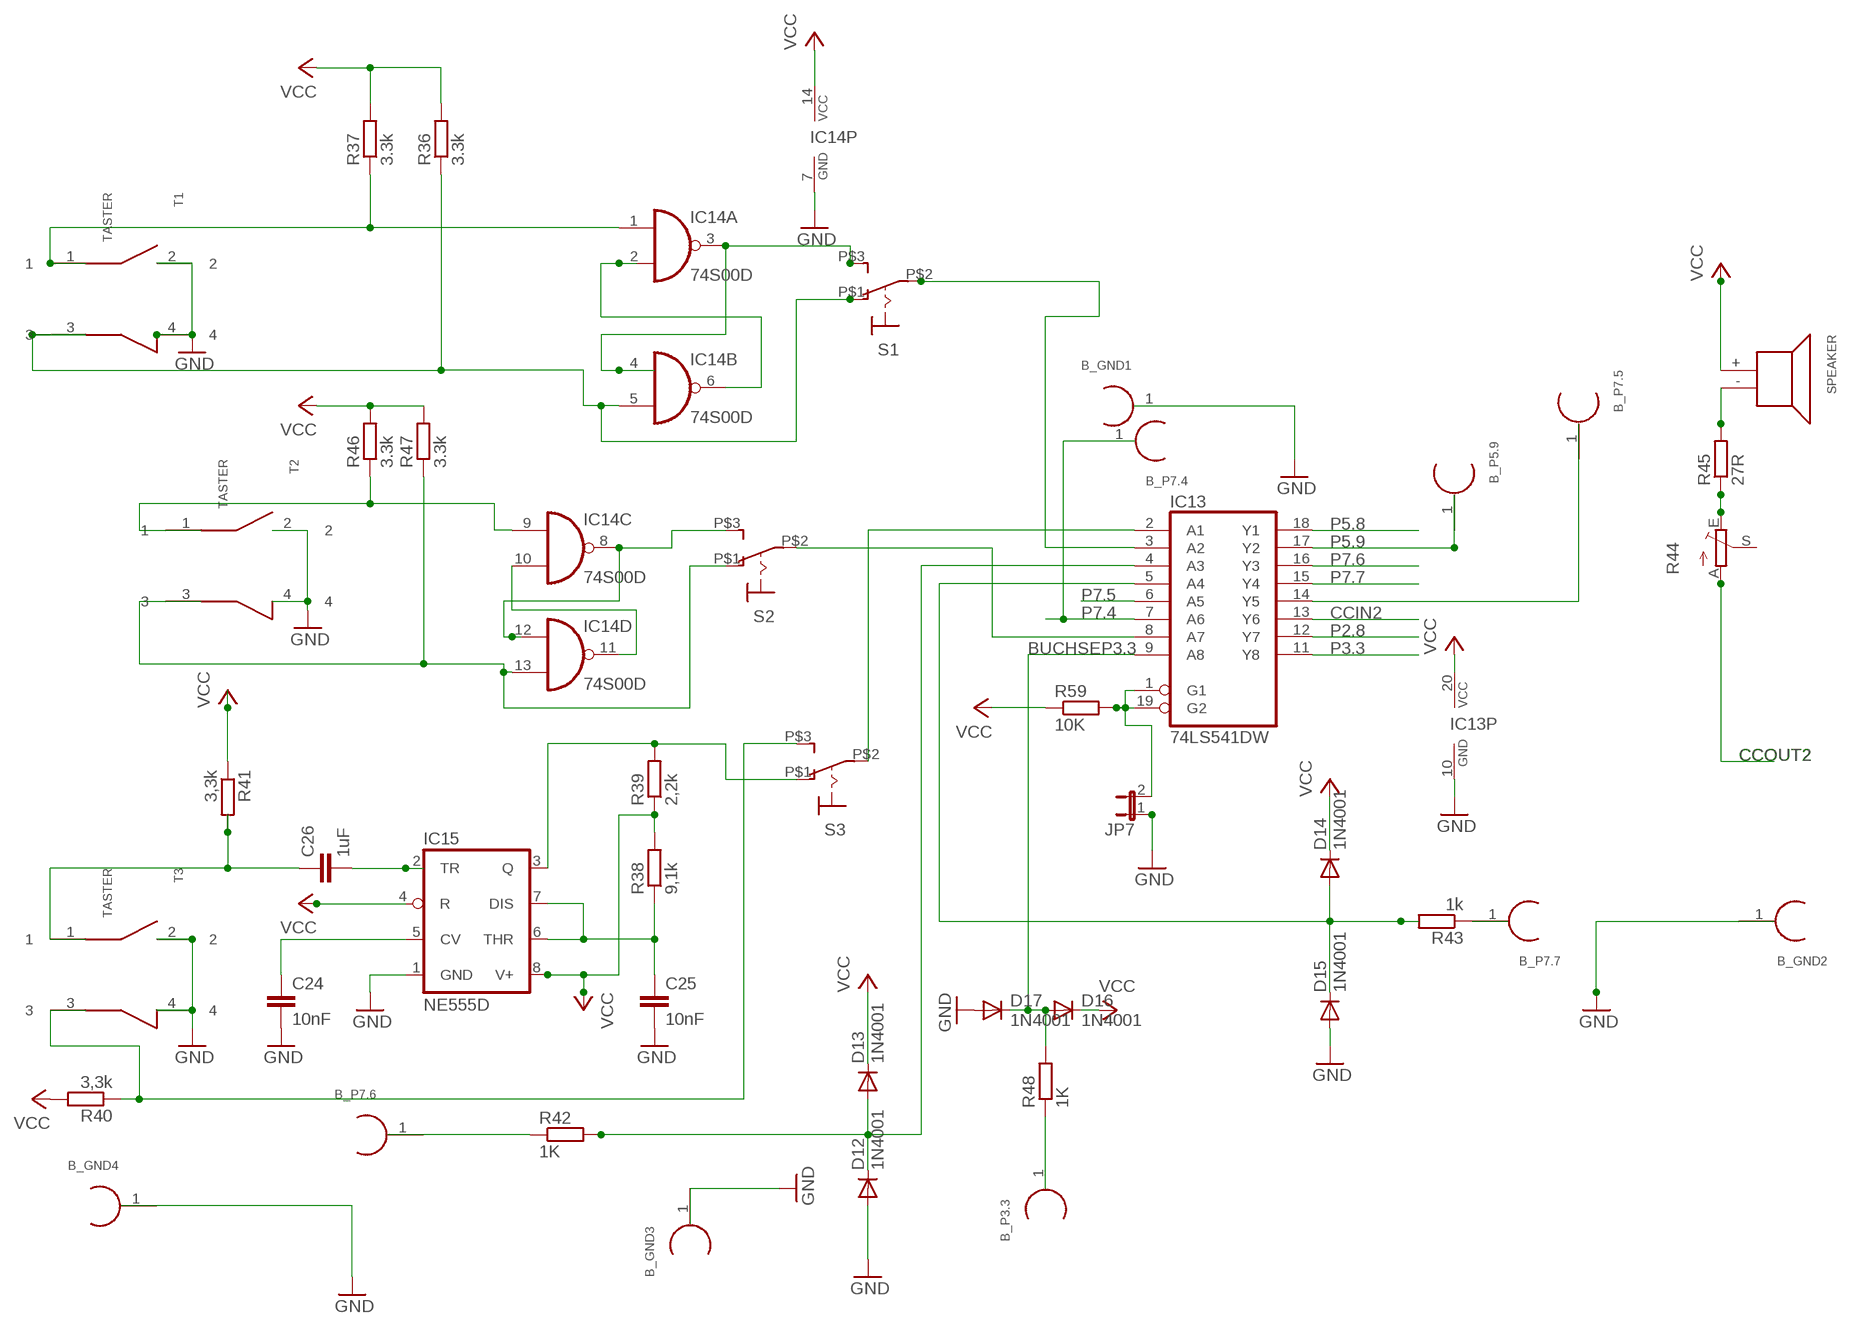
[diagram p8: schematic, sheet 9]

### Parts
B_GND1  BUCHSE01  [BUCHSE01]
B_GND2  BUCHSE01  [BUCHSE01]
B_GND3  BUCHSE01  [BUCHSE01]
B_GND4  BUCHSE01  [BUCHSE01]
B_P3.3  BUCHSE01  [BUCHSE01]
B_P5.9  Buchse P5.9  BUCHSE01  [BUCHSE01]
B_P7.4  BUCHSE01  [BUCHSE01]
B_P7.5  BUCHSE01  [BUCHSE01]
B_P7.6  BUCHSE01  [BUCHSE01]
B_P7.7  BUCHSE01  [BUCHSE01]
C24  10nF  C-EUC0603  [C0603]
C25  10nF  C-EUC0603  [C0603]
C26  1uF  C-EUC0603  [C0603]
D12  1N4001  DIODE-MELF-MLL41  [MELF-MLL41]
D13  1N4001  DIODE-MELF-MLL41  [MELF-MLL41]
D14  1N4001  DIODE-MELF-MLL41  [MELF-MLL41]
D15  1N4001  DIODE-MELF-MLL41  [MELF-MLL41]
D16  1N4001  DIODE-MELF-MLL41  [MELF-MLL41]
D17  1N4001  DIODE-MELF-MLL41  [MELF-MLL41]
IC13  74LS541DW  [SO20W]
IC14  74S00D  [SO14]
IC15  NE555D  [SO08]
JP7  JP1E  [JP1]
R36  3.3k  R-0603  [R0603]
R37  3.3k  R-0603  [R0603]
R38  9,1k  R-0603  [R0603]
R39  2,2k  R-0603  [R0603]
R40  3,3k  R-0603  [R0603]
R41  3,3k  R-0603  [R0603]
R42  1K  R-0603  [R0603]
R43  1k  R-0603  [R0603]
R44  TRIM_EU-LI10  [LI10]
R45  27R  R-0603  [R0603]
R46  3.3k  R-0603  [R0603]
R47  3.3k  R-0603  [R0603]
R48  1K  R-0603  [R0603]
R59  10K  R-0603  [R0603]
S1  SCHIEBESCHALTER_WECHSLER  [SCHIEBESCHALTER]
S2  SCHIEBESCHALTER_WECHSLER  [SCHIEBESCHALTER]
S3  SCHIEBESCHALTER_WECHSLER  [SCHIEBESCHALTER]
SPEAKER  LAUTSPRECHER  [LAUTSPRECHER]
T1  TASTER  [TASTER]
T2  TASTER  [TASTER]
T3  TASTER  [TASTER]

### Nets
BUCHSEP3.3: D16.A D17.C IC13.9(A8) R48.2
CCIN2: IC13.13(Y6) ; also sheet 8
CCOUT2: R44.A ; also sheet 8
GND: B_GND1.1 B_GND2.1 B_GND3.1 B_GND4.1 C24.2 C25.2 D12.A D15.A D17.A IC13.10(GND) IC14.7(P:GND) IC15.1(GND) JP7.1 T1.2 T1.4 T2.2 T2.4 T3.2 T3.4 ; also sheet 1,2,3,5,6,7,8,10,11,12
N: B_P7.5.1 IC13.14(Y5)
N$5: IC14.3(A:O) IC14.4(B:I0) S1.P$3
N$69: IC14.2(A:I1) IC14.6(B:O)
N$79: IC14.1(A:I0) R37.1 T1.1
N$98: IC13.3(A2) S1.P$2
N$103: C24.1 IC15.5(CV)
N$104: C25.1 IC15.6(THR) IC15.7(DIS) R38.1
N$105: IC15.3(Q) R39.2 S3.P$1
N$106: IC13.2(A1) S3.P$2
N$107: C26.2 IC15.2(TR)
N$108: C26.1 R41.2 T3.1
N$109: D12.C D13.A IC13.4(A3) R42.2
N$110: D14.A D15.C IC13.5(A4) R43.2
N$111: B_P7.7.1 R43.1
N$112: R40.1 S3.P$3 T3.3
N$113: R44.E R45.1
N$114: R45.2 SPEAKER.-
N$115: IC14.8(C:O) IC14.12(D:I0) S2.P$3
N$116: IC14.10(C:I1) IC14.11(D:O)
N$117: IC14.13(D:I1) R47.1 S2.P$1 T2.3
N$118: IC14.5(B:I1) R36.1 S1.P$1 T1.3
N$119: IC13.1(G1) IC13.19(G2) JP7.2 R59.2
N$120: IC14.9(C:I0) R46.1 T2.1
N$121: B_P7.6.1 R42.1
N$122: B_P3.3.1 R48.1
N$148: IC13.8(A7) S2.P$2
P2.8: IC13.12(Y7) ; also sheet 1,2
P3.3: IC13.11(Y8) ; also sheet 1,2
P5.8: IC13.18(Y1) ; also sheet 1,2
P5.9: B_P5.9.1 IC13.17(Y2) ; also sheet 1,2
P7.4: B_P7.4.1 IC13.7(A6) ; also sheet 1,2
P7.5: IC13.6(A5) ; also sheet 1,2
P7.6: IC13.16(Y3) ; also sheet 1,2
P7.7: IC13.15(Y4) ; also sheet 1,2
VCC2: D13.C D14.C D16.C IC13.20(VCC) IC14.14(P:VCC) IC15.4(R) IC15.8(V+) R36.2 R37.2 R38.2 R39.1 R40.2 R41.1 R46.2 R47.2 R59.1 SPEAKER.+ ; supply symbol labelled VCC ; also sheet 1,3,4,6,8,10,11
Unconnected: R44.S

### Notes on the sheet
- CCOUT2

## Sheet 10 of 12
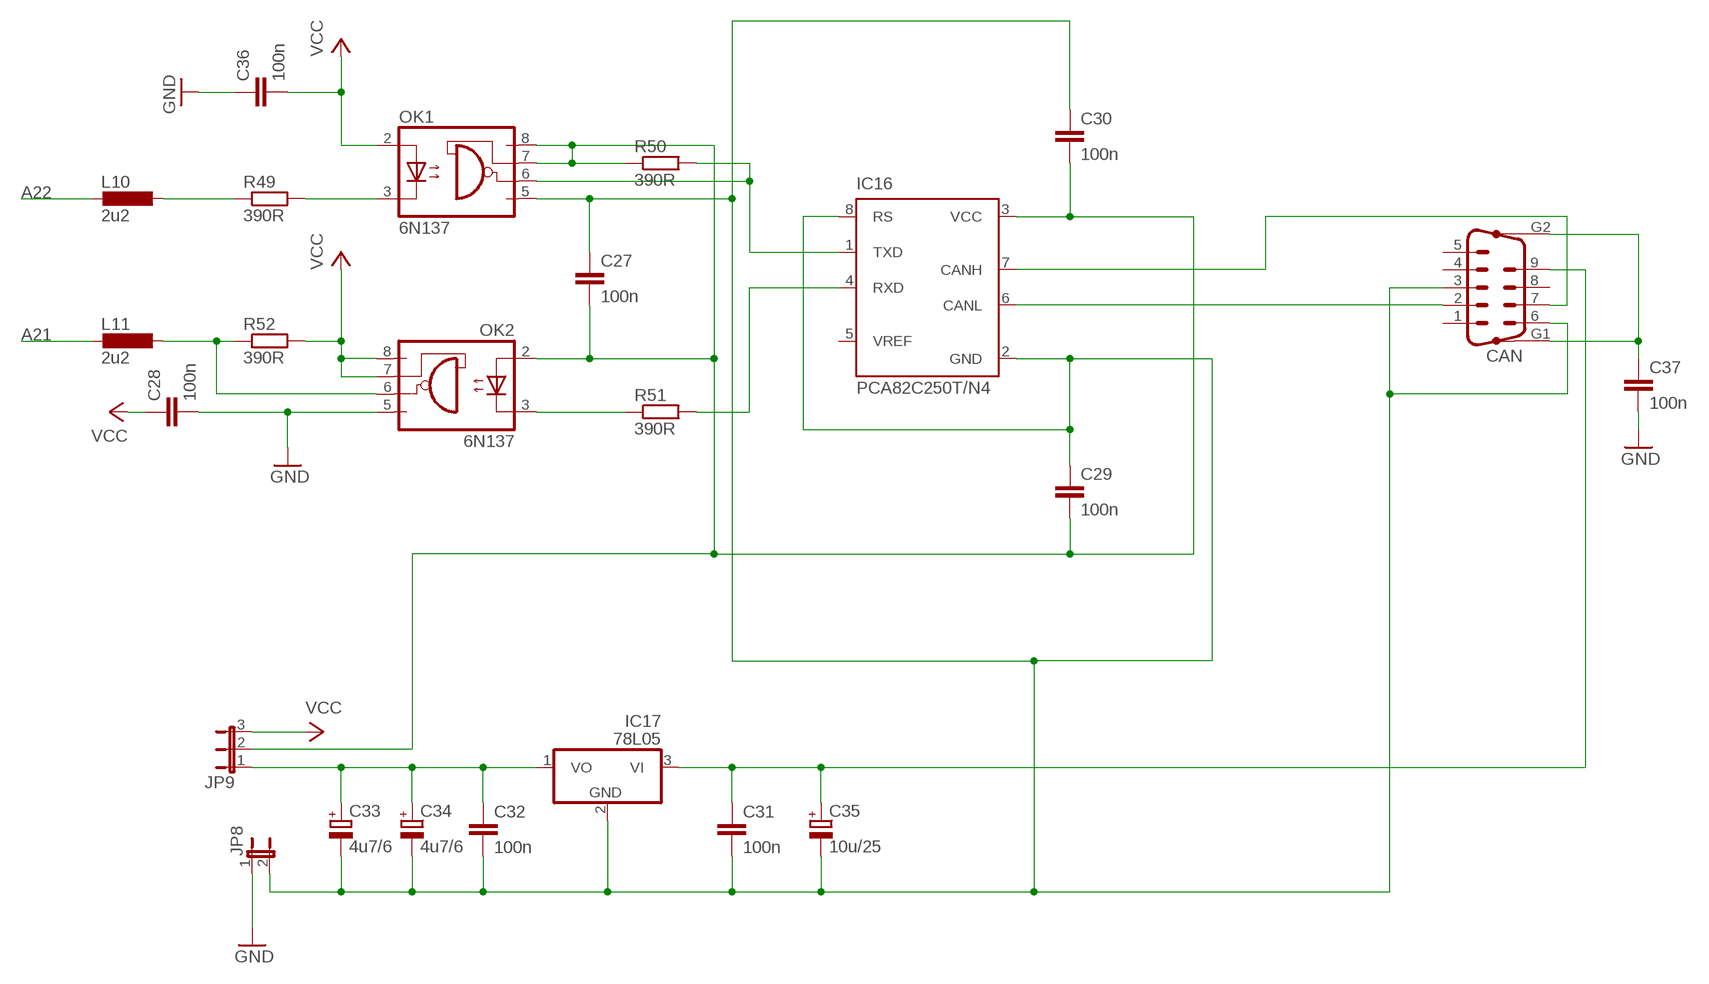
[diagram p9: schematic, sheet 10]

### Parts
C27  100n  C-EUC0603  [C0603]
C28  100n  C-EUC0603  [C0603]
C29  100n  C-EUC0603  [C0603]
C30  100n  C-EUC0603  [C0603]
C31  100n  C-EUC0603  [C0603]
C32  100n  C-EUC0603  [C0603]
C33  4u7/6  CPOL-EUR/2012-12W  [R/2012-12W]
C34  4u7/6  CPOL-EUR/2012-12W  [R/2012-12W]
C35  10u/25  CPOL-EUCT6032  [CT6032]
C36  100n  C-EUC0603  [C0603]
C37  100n  C-EUC0603  [C0603]
CAN  M09HP  [M09HP]
IC16  PCA82C250T/N4  PCA82C250_SMD  [SO8]
IC17  78L05  78L08Z  [TO92]
JP8  JP1E  [JP1]
JP9  JP2E  [JP2]
L10  2u2  L-EUL1812  [L1812]
L11  2u2  L-EUL1812  [L1812]
OK1  6N137  [DIL08]
OK2  6N137  [DIL08]
R49  390R  R-EU_R0603  [R0603]
R50  390R  R-EU_R0603  [R0603]
R51  390R  R-EU_R0603  [R0603]
R52  390R  R-EU_R0603  [R0603]

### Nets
A21: L11.2 ; also sheet 1,2
A22: L10.2 ; also sheet 1,2
CAN5V: C27.2 C29.2 C30.2 IC16.3(VCC) JP9.2 OK1.7(VE) OK1.8(VCC) OK2.2(A) R50.1
CANGND: C27.1 C29.1 C30.1 C31.2 C32.2 C33.- C34.- C35.- CAN.3 CAN.6 IC16.2(GND) IC16.8(RS) IC17.2(GND) JP8.2 OK1.5(GND)
GND: C28.2 C36.1 C37.2 JP8.1 OK2.5(GND) ; also sheet 1,2,3,5,6,7,8,9,11,12
N$123: C32.1 C33.+ C34.+ IC17.1(VO) JP9.1
N$125: OK1.3(C) R49.2
N$126: IC16.1(TXD) OK1.6(VO) R50.2
N$127: OK2.3(C) R51.1
N$128: IC16.4(RXD) R51.2
N$129: L10.1 R49.1
N$130: L11.1 OK2.6(VO) R52.1
N$131: CAN.2 IC16.6(CANL)
N$132: C37.1 CAN.G1 CAN.G2
N$133: CAN.7 IC16.7(CANH)
N$153: C31.1 C35.+ CAN.9 IC17.3(VI)
VCC2: C28.1 C36.2 JP9.3 OK1.2(A) OK2.7(VE) OK2.8(VCC) R52.2 ; supply symbol labelled VCC ; also sheet 1,3,4,6,8,9,11
Unconnected: CAN.1 CAN.4 CAN.5 CAN.8 IC16.5(VREF)

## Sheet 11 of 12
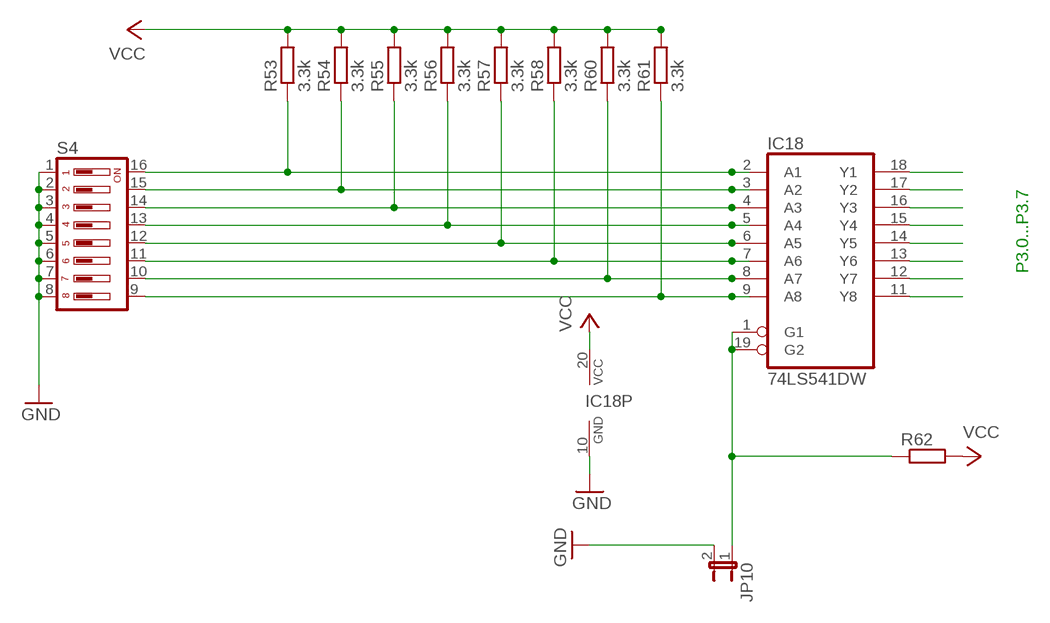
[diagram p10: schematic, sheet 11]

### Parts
IC18  74LS541DW  [SO20W]
JP10  JP1E  [JP1]
R53  3.3k  R-EU_R0603  [R0603]
R54  3.3k  R-EU_R0603  [R0603]
R55  3.3k  R-EU_R0603  [R0603]
R56  3.3k  R-EU_R0603  [R0603]
R57  3.3k  R-EU_R0603  [R0603]
R58  3.3k  R-EU_R0603  [R0603]
R60  3.3k  R-EU_R0603  [R0603]
R61  3.3k  R-EU_R0603  [R0603]
R62  R-0603  [R0603]
S4  DIP08YL  [DIP08YL]

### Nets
GND: IC18.10(GND) JP10.2 S4.1 S4.2 S4.3 S4.4 S4.5 S4.6 S4.7 S4.8 ; also sheet 1,2,3,5,6,7,8,9,10,12
N$134: IC18.2(A1) R53.1 S4.16
N$135: IC18.3(A2) R54.1 S4.15
N$136: IC18.4(A3) R55.1 S4.14
N$137: IC18.5(A4) R56.1 S4.13
N$138: IC18.6(A5) R57.1 S4.12
N$139: IC18.7(A6) R58.1 S4.11
N$140: IC18.8(A7) R60.1 S4.10
N$141: IC18.9(A8) R61.1 S4.9
N$144: IC18.1(G1) IC18.19(G2) JP10.1 R62.1
P3.4: IC18.18(Y1) ; also sheet 1,2
P3.5: IC18.17(Y2) ; also sheet 1,2
P3.6: IC18.16(Y3) ; also sheet 1,2
P3.7: IC18.15(Y4) ; also sheet 1,2
P3.8: IC18.14(Y5) ; also sheet 1,2
P3.9: IC18.13(Y6) ; also sheet 1,2
P3.10: IC18.12(Y7) ; also sheet 1,2
P3.11: IC18.11(Y8) ; also sheet 1,2
VCC2: IC18.20(VCC) R53.2 R54.2 R55.2 R56.2 R57.2 R58.2 R60.2 R61.2 R62.2 ; supply symbol labelled VCC ; also sheet 1,3,4,6,8,9,10

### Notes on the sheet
- P3.0...P3.7

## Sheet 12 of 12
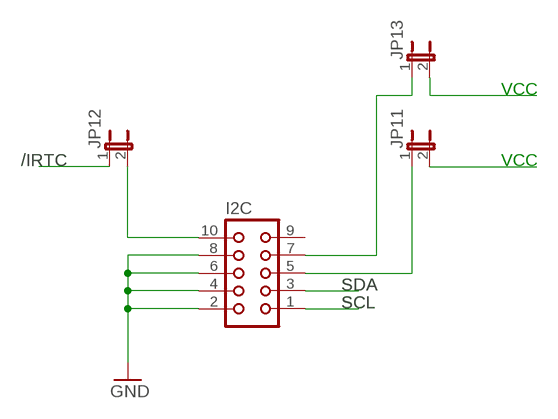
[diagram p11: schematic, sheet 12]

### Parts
I2C  CON10  [CON10]
JP11  JP1E  [JP1]
JP12  JP1E  [JP1]
JP13  JP1E  [JP1]

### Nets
/IRTC: JP12.1 ; also sheet 2
GND: I2C.2 I2C.4 I2C.6 I2C.8 ; also sheet 1,2,3,5,6,7,8,9,10,11
N$145: I2C.5 JP11.1
N$146: I2C.7 JP13.1
N$147: I2C.10 JP12.2
SCL: I2C.1 ; also sheet 2
SDA: I2C.3 ; also sheet 2
VCC3: JP11.2 JP13.2
Unconnected: I2C.9

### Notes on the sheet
- VCC
- /IRTC | VCC
- SDA
- SCL

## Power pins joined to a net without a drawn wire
GND: IC5.7(P:GND) IC6.7(P:GND) IC7.7(P:GND) IC8.7(P:GND)
VCC2: IC5.14(P:VCC) IC6.14(P:VCC) IC7.14(P:VCC) IC8.14(P:VCC)

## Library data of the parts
B1 = eigene:NETZBUCHSE
B2-B7 B_GND1-B_GND4 B_P3.3 B_P5.9 B_P7.4-B_P7.7 = eigene:BUCHSE01: Buchse 2mm
BOOT RESET T1-T3 = eigene:TASTER: Taster 1pol Öffner und 1pol. Schließer
C1-C3 C8-C12 C33-C35 = rcl:CPOL-EU: POLARIZED CAPACITOR, European symbol
C4-C7 C13-C32 C36 C37 = rcl:C-EU: CAPACITOR, European symbol
CAN = con-subd:M09HP: SUB-D
D1-D17 = diode:DIODE-: DIODE
F2 = fuse:SHK20Q: FUSE HOLDER 5 x 20 mm, SH contact, E1207 Buerklin 64G6061
I2C = con-harting:CON10: CONNECTOR
IC1 IC3 = v-reg:78XXS: VOLTAGE REGULATOR
IC2 = v-reg:78LXX: VOLTAGE REGULATOR
IC4 IC17 = linear:78*: Positive VOLTAGE REGULATOR Source: http://cache.national.com/ds/LM/LM78L05.pdf http://www.fairchildsemi.com/ds/LM/LM7805.pdf
IC5-IC8 IC14 = 74xx-eu:74*00: Quad 2-input NAND gate
IC9 IC10 IC13 IC18 = 74xx-eu:74*541: Octal BUFFER and LINE DRIVER, 3-state
IC11 IC12 = uln-udn:ULN2003A: DRIVER ARRAY
IC15 = linear:*555: TIMER
IC16 = micro-philips2:PCA82C250_SMD
JP1 JP2 JP6-JP8 JP10-JP13 = jumper:JP1E: JUMPER
JP3-JP5 = eigene:CONN_50POL
JP9 = jumper:JP2E: JUMPER
KIPP1-KIPP8 U$1 U$2 = Knitter-Switch:ATE1
L1-L11 = rcl:L-EU: INDUCTOR, European symbol
LED1-LED9 = led:LED: LED
MM_C1 = phytec:MM_C167: Minimodul Phytec C167
OK1 OK2 = optocoupler:6N137: MOTOROLA OPTO COUPLER
R1 R5 R6 R44 = pot:TRIM_EU-: POTENTIOMETER
R2-R4 R7 R25 R26 R49-R58 R60 R61 = rcl:R-EU_: RESISTOR, European symbol
R8-R24 R27-R43 R45-R48 R59 R62 = quantum-sensor:R: Resistor
RS232_1 RS232_2 = con-subd:F09HP: SUB-D
S1-S3 SCHIEB1-SCHIEB8 = eigene:SCHIEBESCHALTER_WECHSLER
S4 = eigene:DIP08YL: DIL/CODE SWITCH
SPEAKER = eigene:LAUTSPRECHER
